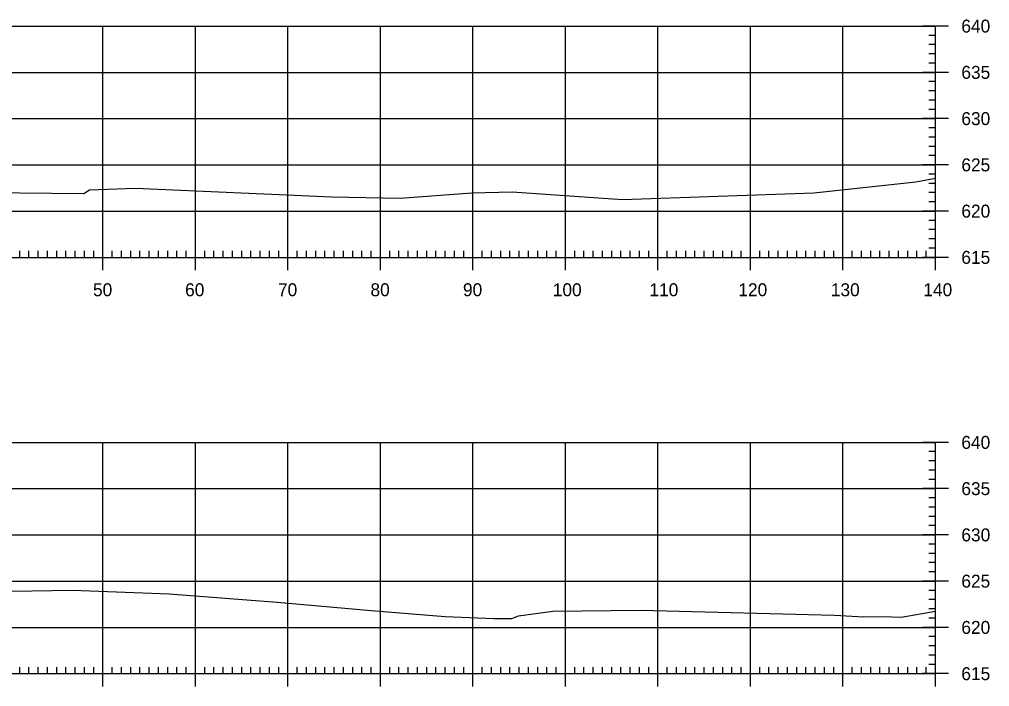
# Model space of a CAD drawing. Extents: x 1381471 to 1382703, y 370300 to 371487.
# Drawn here: x 1382177.6 to 1382282.5, y 370697.4 to 370769.5 of the extents above; entities that cross this region are included whole.
import ezdxf

# ---------------------------------------------------------------- set-up
doc = ezdxf.new("R2010")
doc.units = 0
doc.layers.add('Level 45', color=7, linetype='Continuous')

msp = doc.modelspace()

# ---------------------------------------------------------------- linework, layer by layer
at = {"layer": 'Level 45'}
for p, q in [((1381996.61, 370768.78), (1382276.61, 370768.78)), ((1382186.61, 370743.78), (1382186.61, 370768.78)), ((1382196.61, 370743.78), (1382196.61, 370768.78)), ((1382206.61, 370743.78), (1382206.61, 370768.78)), ((1382216.61, 370743.78), (1382216.61, 370768.78)), ((1382226.61, 370743.78), (1382226.61, 370768.78)), ((1382236.61, 370743.78), (1382236.61, 370768.78)), ((1382246.61, 370743.78), (1382246.61, 370768.78)), ((1382256.61, 370743.78), (1382256.61, 370768.78)), ((1382266.61, 370743.78), (1382266.61, 370768.78)), ((1382278.01, 370768.78), (1382275.21, 370768.78)), ((1382276.61, 370743.78), (1382276.61, 370768.78)), ((1382276.61, 370743.78), (1382276.61, 370768.78)), ((1382276.61, 370767.78), (1382275.91, 370767.78)), ((1382276.61, 370766.78), (1382275.91, 370766.78)), ((1382276.61, 370765.78), (1382275.91, 370765.78)), ((1382276.61, 370764.78), (1382275.91, 370764.78)), ((1381996.61, 370763.78), (1382276.61, 370763.78)), ((1382278.01, 370763.78), (1382275.21, 370763.78)), ((1382276.61, 370762.78), (1382275.91, 370762.78)), ((1382276.61, 370761.78), (1382275.91, 370761.78)), ((1382276.61, 370760.78), (1382275.91, 370760.78)), ((1382276.61, 370759.78), (1382275.91, 370759.78)), ((1381996.61, 370758.78), (1382276.61, 370758.78)), ((1382278.01, 370758.78), (1382275.21, 370758.78)), ((1382276.61, 370757.78), (1382275.91, 370757.78)), ((1382276.61, 370756.78), (1382275.91, 370756.78)), ((1382276.61, 370755.78), (1382275.91, 370755.78)), ((1382276.61, 370754.78), (1382275.91, 370754.78)), ((1381996.61, 370753.78), (1382276.61, 370753.78)), ((1382278.01, 370753.78), (1382275.21, 370753.78)), ((1382276.61, 370752.78), (1382275.91, 370752.78)), ((1382276.61, 370751.78), (1382275.91, 370751.78)), ((1382276.61, 370750.78), (1382275.91, 370750.78)), ((1382276.61, 370749.78), (1382275.91, 370749.78)), ((1381996.61, 370748.78), (1382276.61, 370748.78)), ((1382278.01, 370748.78), (1382275.21, 370748.78)), ((1382276.61, 370747.78), (1382275.91, 370747.78)), ((1382276.61, 370746.78), (1382275.91, 370746.78)), ((1382186.61, 370742.38), (1382186.61, 370745.18)), ((1382196.61, 370742.38), (1382196.61, 370745.18)), ((1382206.61, 370742.38), (1382206.61, 370745.18)), ((1382216.61, 370742.38), (1382216.61, 370745.18)), ((1382226.61, 370742.38), (1382226.61, 370745.18)), ((1382236.61, 370742.38), (1382236.61, 370745.18)), ((1382246.61, 370742.38), (1382246.61, 370745.18)), ((1382256.61, 370742.38), (1382256.61, 370745.18)), ((1382266.61, 370742.38), (1382266.61, 370745.18)), ((1382276.61, 370745.78), (1382275.91, 370745.78)), ((1382276.61, 370742.38), (1382276.61, 370745.18)), ((1382177.61, 370743.78), (1382177.61, 370744.48)), ((1382178.61, 370743.78), (1382178.61, 370744.48)), ((1382179.61, 370743.78), (1382179.61, 370744.48)), ((1382180.61, 370743.78), (1382180.61, 370744.48)), ((1382181.61, 370743.78), (1382181.61, 370744.48)), ((1382182.61, 370743.78), (1382182.61, 370744.48)), ((1382183.61, 370743.78), (1382183.61, 370744.48)), ((1382184.61, 370743.78), (1382184.61, 370744.48)), ((1382185.61, 370743.78), (1382185.61, 370744.48)), ((1382187.61, 370743.78), (1382187.61, 370744.48)), ((1382188.61, 370743.78), (1382188.61, 370744.48)), ((1382189.61, 370743.78), (1382189.61, 370744.48)), ((1382190.61, 370743.78), (1382190.61, 370744.48)), ((1382191.61, 370743.78), (1382191.61, 370744.48)), ((1382192.61, 370743.78), (1382192.61, 370744.48)), ((1382193.61, 370743.78), (1382193.61, 370744.48)), ((1382194.61, 370743.78), (1382194.61, 370744.48)), ((1382195.61, 370743.78), (1382195.61, 370744.48)), ((1382197.61, 370743.78), (1382197.61, 370744.48)), ((1382198.61, 370743.78), (1382198.61, 370744.48)), ((1382199.61, 370743.78), (1382199.61, 370744.48)), ((1382200.61, 370743.78), (1382200.61, 370744.48)), ((1382201.61, 370743.78), (1382201.61, 370744.48)), ((1382202.61, 370743.78), (1382202.61, 370744.48)), ((1382203.61, 370743.78), (1382203.61, 370744.48)), ((1382204.61, 370743.78), (1382204.61, 370744.48)), ((1382205.61, 370743.78), (1382205.61, 370744.48)), ((1382207.61, 370743.78), (1382207.61, 370744.48)), ((1382208.61, 370743.78), (1382208.61, 370744.48)), ((1382209.61, 370743.78), (1382209.61, 370744.48)), ((1382210.61, 370743.78), (1382210.61, 370744.48)), ((1382211.61, 370743.78), (1382211.61, 370744.48)), ((1382212.61, 370743.78), (1382212.61, 370744.48)), ((1382213.61, 370743.78), (1382213.61, 370744.48)), ((1382214.61, 370743.78), (1382214.61, 370744.48)), ((1382215.61, 370743.78), (1382215.61, 370744.48)), ((1382217.61, 370743.78), (1382217.61, 370744.48)), ((1382218.61, 370743.78), (1382218.61, 370744.48)), ((1382219.61, 370743.78), (1382219.61, 370744.48)), ((1382220.61, 370743.78), (1382220.61, 370744.48)), ((1382221.61, 370743.78), (1382221.61, 370744.48)), ((1382222.61, 370743.78), (1382222.61, 370744.48)), ((1382223.61, 370743.78), (1382223.61, 370744.48)), ((1382224.61, 370743.78), (1382224.61, 370744.48)), ((1382225.61, 370743.78), (1382225.61, 370744.48)), ((1382227.61, 370743.78), (1382227.61, 370744.48)), ((1382228.61, 370743.78), (1382228.61, 370744.48)), ((1382229.61, 370743.78), (1382229.61, 370744.48)), ((1382230.61, 370743.78), (1382230.61, 370744.48)), ((1382231.61, 370743.78), (1382231.61, 370744.48)), ((1382232.61, 370743.78), (1382232.61, 370744.48)), ((1382233.61, 370743.78), (1382233.61, 370744.48)), ((1382234.61, 370743.78), (1382234.61, 370744.48)), ((1382235.61, 370743.78), (1382235.61, 370744.48)), ((1382237.61, 370743.78), (1382237.61, 370744.48)), ((1382238.61, 370743.78), (1382238.61, 370744.48)), ((1382239.61, 370743.78), (1382239.61, 370744.48)), ((1382240.61, 370743.78), (1382240.61, 370744.48)), ((1382241.61, 370743.78), (1382241.61, 370744.48)), ((1382242.61, 370743.78), (1382242.61, 370744.48)), ((1382243.61, 370743.78), (1382243.61, 370744.48)), ((1382244.61, 370743.78), (1382244.61, 370744.48)), ((1382245.61, 370743.78), (1382245.61, 370744.48)), ((1382247.61, 370743.78), (1382247.61, 370744.48)), ((1382248.61, 370743.78), (1382248.61, 370744.48)), ((1382249.61, 370743.78), (1382249.61, 370744.48)), ((1382250.61, 370743.78), (1382250.61, 370744.48)), ((1382251.61, 370743.78), (1382251.61, 370744.48)), ((1382252.61, 370743.78), (1382252.61, 370744.48)), ((1382253.61, 370743.78), (1382253.61, 370744.48)), ((1382254.61, 370743.78), (1382254.61, 370744.48)), ((1382255.61, 370743.78), (1382255.61, 370744.48)), ((1382257.61, 370743.78), (1382257.61, 370744.48)), ((1382258.61, 370743.78), (1382258.61, 370744.48)), ((1382259.61, 370743.78), (1382259.61, 370744.48)), ((1382260.61, 370743.78), (1382260.61, 370744.48)), ((1382261.61, 370743.78), (1382261.61, 370744.48)), ((1382262.61, 370743.78), (1382262.61, 370744.48)), ((1382263.61, 370743.78), (1382263.61, 370744.48)), ((1382264.61, 370743.78), (1382264.61, 370744.48)), ((1382265.61, 370743.78), (1382265.61, 370744.48)), ((1382267.61, 370743.78), (1382267.61, 370744.48)), ((1382268.61, 370743.78), (1382268.61, 370744.48)), ((1382269.61, 370743.78), (1382269.61, 370744.48)), ((1382270.61, 370743.78), (1382270.61, 370744.48)), ((1382271.61, 370743.78), (1382271.61, 370744.48)), ((1382272.61, 370743.78), (1382272.61, 370744.48)), ((1382273.61, 370743.78), (1382273.61, 370744.48)), ((1382274.61, 370743.78), (1382274.61, 370744.48)), ((1382275.61, 370743.78), (1382275.61, 370744.48)), ((1382276.61, 370744.78), (1382275.91, 370744.78)), ((1381996.61, 370743.78), (1382276.61, 370743.78)), ((1381996.61, 370743.78), (1382276.61, 370743.78)), ((1382278.01, 370743.78), (1382275.21, 370743.78)), ((1381996.61, 370723.78), (1382276.61, 370723.78)), ((1382186.61, 370698.78), (1382186.61, 370723.78)), ((1382196.61, 370698.78), (1382196.61, 370723.78)), ((1382206.61, 370698.78), (1382206.61, 370723.78)), ((1382216.61, 370698.78), (1382216.61, 370723.78)), ((1382226.61, 370698.78), (1382226.61, 370723.78)), ((1382236.61, 370698.78), (1382236.61, 370723.78)), ((1382246.61, 370698.78), (1382246.61, 370723.78)), ((1382256.61, 370698.78), (1382256.61, 370723.78)), ((1382266.61, 370698.78), (1382266.61, 370723.78)), ((1382278.01, 370723.78), (1382275.21, 370723.78)), ((1382276.61, 370698.78), (1382276.61, 370723.78)), ((1382276.61, 370698.78), (1382276.61, 370723.78)), ((1382276.61, 370722.78), (1382275.91, 370722.78)), ((1382276.61, 370721.78), (1382275.91, 370721.78)), ((1382276.61, 370720.78), (1382275.91, 370720.78)), ((1382276.61, 370719.78), (1382275.91, 370719.78)), ((1381996.61, 370718.78), (1382276.61, 370718.78)), ((1382278.01, 370718.78), (1382275.21, 370718.78)), ((1382276.61, 370717.78), (1382275.91, 370717.78)), ((1382276.61, 370716.78), (1382275.91, 370716.78)), ((1382276.61, 370715.78), (1382275.91, 370715.78)), ((1382276.61, 370714.78), (1382275.91, 370714.78)), ((1381996.61, 370713.78), (1382276.61, 370713.78)), ((1382278.01, 370713.78), (1382275.21, 370713.78)), ((1382276.61, 370712.78), (1382275.91, 370712.78)), ((1382276.61, 370711.78), (1382275.91, 370711.78)), ((1382276.61, 370710.78), (1382275.91, 370710.78)), ((1382276.61, 370709.78), (1382275.91, 370709.78)), ((1381996.61, 370708.78), (1382276.61, 370708.78)), ((1382278.01, 370708.78), (1382275.21, 370708.78)), ((1382276.61, 370707.78), (1382275.91, 370707.78)), ((1382276.61, 370706.78), (1382275.91, 370706.78)), ((1382276.61, 370705.78), (1382275.91, 370705.78)), ((1382276.61, 370704.78), (1382275.91, 370704.78)), ((1381996.61, 370703.78), (1382276.61, 370703.78)), ((1382278.01, 370703.78), (1382275.21, 370703.78)), ((1382276.61, 370702.78), (1382275.91, 370702.78)), ((1382276.61, 370701.78), (1382275.91, 370701.78)), ((1382186.61, 370697.38), (1382186.61, 370700.18)), ((1382196.61, 370697.38), (1382196.61, 370700.18)), ((1382206.61, 370697.38), (1382206.61, 370700.18)), ((1382216.61, 370697.38), (1382216.61, 370700.18)), ((1382226.61, 370697.38), (1382226.61, 370700.18)), ((1382236.61, 370697.38), (1382236.61, 370700.18)), ((1382246.61, 370697.38), (1382246.61, 370700.18)), ((1382256.61, 370697.38), (1382256.61, 370700.18)), ((1382266.61, 370697.38), (1382266.61, 370700.18)), ((1382276.61, 370700.78), (1382275.91, 370700.78)), ((1382276.61, 370697.38), (1382276.61, 370700.18)), ((1381996.61, 370698.78), (1382276.61, 370698.78)), ((1381996.61, 370698.78), (1382276.61, 370698.78)), ((1382177.61, 370698.78), (1382177.61, 370699.48)), ((1382178.61, 370698.78), (1382178.61, 370699.48)), ((1382179.61, 370698.78), (1382179.61, 370699.48)), ((1382180.61, 370698.78), (1382180.61, 370699.48)), ((1382181.61, 370698.78), (1382181.61, 370699.48)), ((1382182.61, 370698.78), (1382182.61, 370699.48)), ((1382183.61, 370698.78), (1382183.61, 370699.48)), ((1382184.61, 370698.78), (1382184.61, 370699.48)), ((1382185.61, 370698.78), (1382185.61, 370699.48)), ((1382187.61, 370698.78), (1382187.61, 370699.48)), ((1382188.61, 370698.78), (1382188.61, 370699.48)), ((1382189.61, 370698.78), (1382189.61, 370699.48)), ((1382190.61, 370698.78), (1382190.61, 370699.48)), ((1382191.61, 370698.78), (1382191.61, 370699.48)), ((1382192.61, 370698.78), (1382192.61, 370699.48)), ((1382193.61, 370698.78), (1382193.61, 370699.48)), ((1382194.61, 370698.78), (1382194.61, 370699.48)), ((1382195.61, 370698.78), (1382195.61, 370699.48)), ((1382197.61, 370698.78), (1382197.61, 370699.48)), ((1382198.61, 370698.78), (1382198.61, 370699.48)), ((1382199.61, 370698.78), (1382199.61, 370699.48)), ((1382200.61, 370698.78), (1382200.61, 370699.48)), ((1382201.61, 370698.78), (1382201.61, 370699.48)), ((1382202.61, 370698.78), (1382202.61, 370699.48)), ((1382203.61, 370698.78), (1382203.61, 370699.48)), ((1382204.61, 370698.78), (1382204.61, 370699.48)), ((1382205.61, 370698.78), (1382205.61, 370699.48)), ((1382207.61, 370698.78), (1382207.61, 370699.48)), ((1382208.61, 370698.78), (1382208.61, 370699.48)), ((1382209.61, 370698.78), (1382209.61, 370699.48)), ((1382210.61, 370698.78), (1382210.61, 370699.48)), ((1382211.61, 370698.78), (1382211.61, 370699.48)), ((1382212.61, 370698.78), (1382212.61, 370699.48)), ((1382213.61, 370698.78), (1382213.61, 370699.48)), ((1382214.61, 370698.78), (1382214.61, 370699.48)), ((1382215.61, 370698.78), (1382215.61, 370699.48)), ((1382217.61, 370698.78), (1382217.61, 370699.48)), ((1382218.61, 370698.78), (1382218.61, 370699.48)), ((1382219.61, 370698.78), (1382219.61, 370699.48)), ((1382220.61, 370698.78), (1382220.61, 370699.48)), ((1382221.61, 370698.78), (1382221.61, 370699.48)), ((1382222.61, 370698.78), (1382222.61, 370699.48)), ((1382223.61, 370698.78), (1382223.61, 370699.48)), ((1382224.61, 370698.78), (1382224.61, 370699.48)), ((1382225.61, 370698.78), (1382225.61, 370699.48)), ((1382227.61, 370698.78), (1382227.61, 370699.48)), ((1382228.61, 370698.78), (1382228.61, 370699.48)), ((1382229.61, 370698.78), (1382229.61, 370699.48)), ((1382230.61, 370698.78), (1382230.61, 370699.48)), ((1382231.61, 370698.78), (1382231.61, 370699.48)), ((1382232.61, 370698.78), (1382232.61, 370699.48)), ((1382233.61, 370698.78), (1382233.61, 370699.48)), ((1382234.61, 370698.78), (1382234.61, 370699.48)), ((1382235.61, 370698.78), (1382235.61, 370699.48)), ((1382237.61, 370698.78), (1382237.61, 370699.48)), ((1382238.61, 370698.78), (1382238.61, 370699.48)), ((1382239.61, 370698.78), (1382239.61, 370699.48)), ((1382240.61, 370698.78), (1382240.61, 370699.48)), ((1382241.61, 370698.78), (1382241.61, 370699.48)), ((1382242.61, 370698.78), (1382242.61, 370699.48)), ((1382243.61, 370698.78), (1382243.61, 370699.48)), ((1382244.61, 370698.78), (1382244.61, 370699.48)), ((1382245.61, 370698.78), (1382245.61, 370699.48)), ((1382247.61, 370698.78), (1382247.61, 370699.48)), ((1382248.61, 370698.78), (1382248.61, 370699.48)), ((1382249.61, 370698.78), (1382249.61, 370699.48)), ((1382250.61, 370698.78), (1382250.61, 370699.48)), ((1382251.61, 370698.78), (1382251.61, 370699.48)), ((1382252.61, 370698.78), (1382252.61, 370699.48)), ((1382253.61, 370698.78), (1382253.61, 370699.48)), ((1382254.61, 370698.78), (1382254.61, 370699.48)), ((1382255.61, 370698.78), (1382255.61, 370699.48)), ((1382257.61, 370698.78), (1382257.61, 370699.48)), ((1382258.61, 370698.78), (1382258.61, 370699.48)), ((1382259.61, 370698.78), (1382259.61, 370699.48)), ((1382260.61, 370698.78), (1382260.61, 370699.48)), ((1382261.61, 370698.78), (1382261.61, 370699.48)), ((1382262.61, 370698.78), (1382262.61, 370699.48)), ((1382263.61, 370698.78), (1382263.61, 370699.48)), ((1382264.61, 370698.78), (1382264.61, 370699.48)), ((1382265.61, 370698.78), (1382265.61, 370699.48)), ((1382267.61, 370698.78), (1382267.61, 370699.48)), ((1382268.61, 370698.78), (1382268.61, 370699.48)), ((1382269.61, 370698.78), (1382269.61, 370699.48)), ((1382270.61, 370698.78), (1382270.61, 370699.48)), ((1382271.61, 370698.78), (1382271.61, 370699.48)), ((1382272.61, 370698.78), (1382272.61, 370699.48)), ((1382273.61, 370698.78), (1382273.61, 370699.48)), ((1382274.61, 370698.78), (1382274.61, 370699.48)), ((1382278.01, 370698.78), (1382275.21, 370698.78)), ((1382275.61, 370698.78), (1382275.61, 370699.48)), ((1382276.61, 370699.78), (1382275.91, 370699.78))]:
    msp.add_line(p, q, dxfattribs=at)
for points in [[(1382170.64, 370750.82), (1382184.54, 370750.7), (1382185.17, 370751.07), (1382190.14, 370751.25), (1382211.37, 370750.33), (1382218.73, 370750.18), (1382226.49, 370750.74), (1382230.84, 370750.86), (1382242.79, 370750.02), (1382263.47, 370750.76), (1382274.48, 370751.93), (1382276.61, 370752.33)], [(1382172.25, 370707.63), (1382183.31, 370707.81), (1382193.76, 370707.4), (1382205.46, 370706.52), (1382215.59, 370705.6), (1382223.6, 370704.95), (1382228.87, 370704.76), (1382230.83, 370704.75), (1382231.53, 370705.03), (1382235.23, 370705.54), (1382244.74, 370705.65), (1382265.68, 370705.09), (1382268.88, 370704.94), (1382270.98, 370704.95), (1382272.9, 370704.9), (1382276.61, 370705.55)]]:
    msp.add_lwpolyline(points, dxfattribs=at)

# ---------------------------------------------------------------- texts
for s, p in [('640', (1382279.41, 370768.08)), ('635', (1382279.41, 370763.08)), ('630', (1382279.41, 370758.08)), ('625', (1382279.41, 370753.08)), ('620', (1382279.41, 370748.08)), ('615', (1382279.41, 370743.08)), ('50', (1382185.53, 370739.58)), ('60', (1382195.49, 370739.58)), ('70', (1382205.53, 370739.58)), ('80', (1382215.53, 370739.58)), ('90', (1382225.53, 370739.58)), ('100', (1382235.24, 370739.58)), ('110', (1382245.69, 370739.58)), ('120', (1382255.3, 370739.58)), ('130', (1382265.3, 370739.58)), ('140', (1382275.3, 370739.58)), ('640', (1382279.41, 370723.08)), ('635', (1382279.41, 370718.08)), ('630', (1382279.41, 370713.08)), ('625', (1382279.41, 370708.08)), ('620', (1382279.41, 370703.08)), ('615', (1382279.41, 370698.08))]:
    msp.add_text(s, height=1.4, dxfattribs=at).set_placement(p)

doc.saveas('drawing.dxf')
